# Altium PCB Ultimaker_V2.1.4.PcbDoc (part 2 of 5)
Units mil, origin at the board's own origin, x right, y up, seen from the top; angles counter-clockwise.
Board outline 6889.76 x 3110.24 mil, 4 copper layers (top, signal, Power, bot (thermal)), stack 67.717 mil thick; 574 components, 252 nets, 1322 pads, 511 vias.
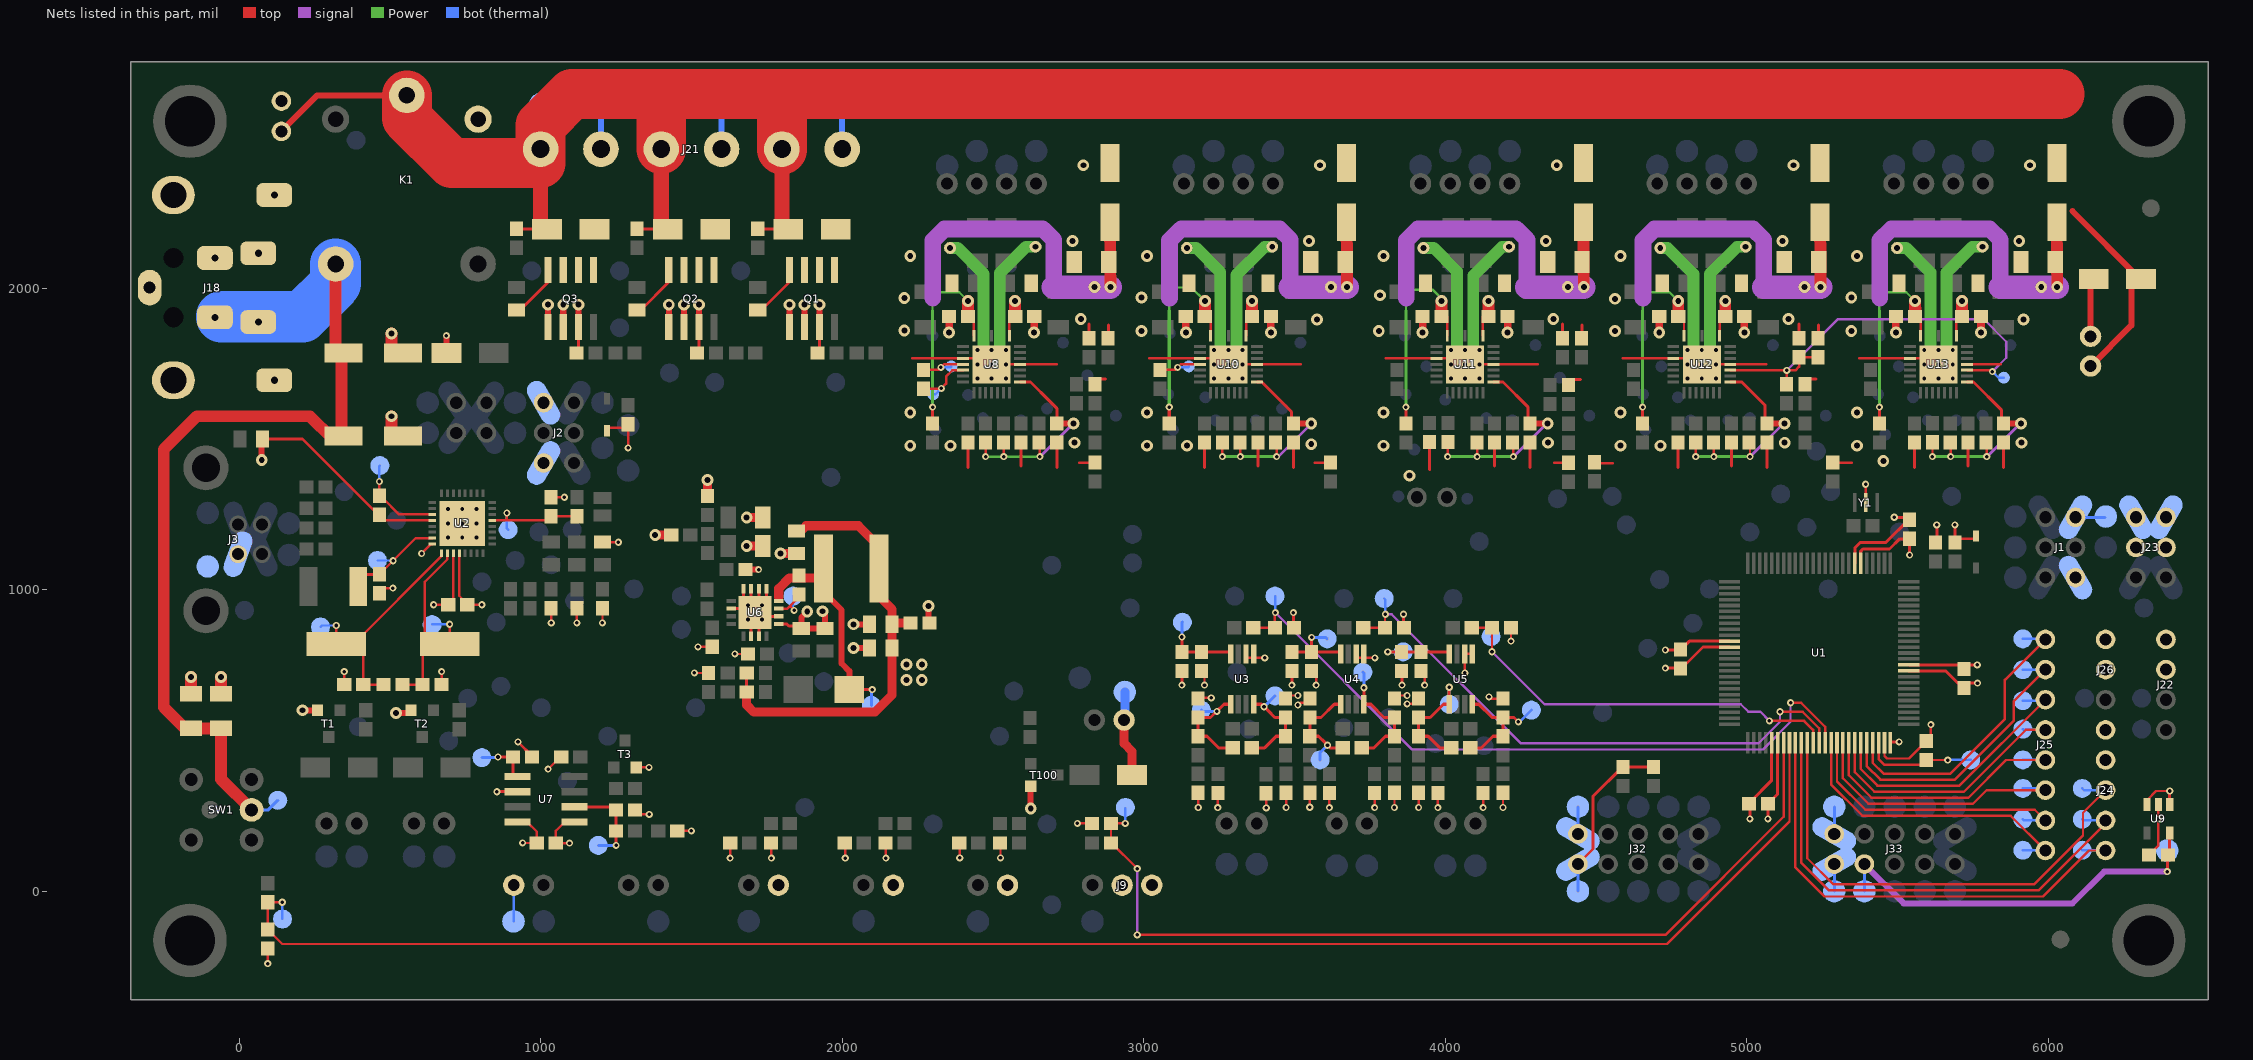
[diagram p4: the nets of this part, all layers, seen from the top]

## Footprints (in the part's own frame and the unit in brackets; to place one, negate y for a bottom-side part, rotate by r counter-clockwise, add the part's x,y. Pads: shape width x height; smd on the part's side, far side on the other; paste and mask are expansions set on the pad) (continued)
TSQFP50P1600X1600X120-100N [mm] "TSQFP, 100-Leads, Body 16.3x16.3mm (max), Pitch 0.50mm, IPC Medium Density"
  rect 1.8x0.3 smd: 1(-7.55,6) 2(-7.55,5.5) 3(-7.55,5) 4(-7.55,4.5) 5(-7.55,4) 6(-7.55,3.5) 7(-7.55,3) 8(-7.55,2.5) 9(-7.55,2) 10(-7.55,1.5) 11(-7.55,1) 12(-7.55,0.5) 13(-7.55,0) 14(-7.55,-0.5) 15(-7.55,-1) 16(-7.55,-1.5) 17(-7.55,-2) 18(-7.55,-2.5) 19(-7.55,-3) 20(-7.55,-3.5) 21(-7.55,-4) 22(-7.55,-4.5) 23(-7.55,-5) 24(-7.55,-5.5) 25(-7.55,-6) 51(7.55,-6) 52(7.55,-5.5) 53(7.55,-5) 54(7.55,-4.5) 55(7.55,-4) 56(7.55,-3.5) 57(7.55,-3) 58(7.55,-2.5) 59(7.55,-2) 60(7.55,-1.5) 61(7.55,-1) 62(7.55,-0.5) 63(7.55,0) 64(7.55,0.5) 65(7.55,1) 66(7.55,1.5) 67(7.55,2) 68(7.55,2.5) 69(7.55,3) 70(7.55,3.5) 71(7.55,4) 72(7.55,4.5) 73(7.55,5) 74(7.55,5.5) 75(7.55,6)
  rect 0.3x1.8 smd: 26(-6,-7.55) 27(-5.5,-7.55) 28(-5,-7.55) 29(-4.5,-7.55) 30(-4,-7.55) 31(-3.5,-7.55) 32(-3,-7.55) 33(-2.5,-7.55) 34(-2,-7.55) 35(-1.5,-7.55) 36(-1,-7.55) 37(-0.5,-7.55) 38(0,-7.55) 39(0.5,-7.55) 40(1,-7.55) 41(1.5,-7.55) 42(2,-7.55) 43(2.5,-7.55) 44(3,-7.55) 45(3.5,-7.55) 46(4,-7.55) 47(4.5,-7.55) 48(5,-7.55) 49(5.5,-7.55) 50(6,-7.55) 76(6,7.55) 77(5.5,7.55) 78(5,7.55) 79(4.5,7.55) 80(4,7.55) 81(3.5,7.55) 82(3,7.55) 83(2.5,7.55) 84(2,7.55) 85(1.5,7.55) 86(1,7.55) 87(0.5,7.55) 88(0,7.55) 89(-0.5,7.55) 90(-1,7.55) 91(-1.5,7.55) 92(-2,7.55) 93(-2.5,7.55) 94(-3,7.55) 95(-3.5,7.55) 96(-4,7.55) 97(-4.5,7.55) 98(-5,7.55) 99(-5.5,7.55) 100(-6,7.55)
  silkscreen extent -7.68,-6.25 6.25,6.82, body extent -8.01,-8.01 8.01,8.01, height 1.1
XT49M-2016M [mm]
  rect 5x2 smd: 1(-4.775,0) 2(4.775,0)
  silkscreen extent -6.35,-2.35 6.35,2.35, body extent -6.35,-2.35 6.35,2.35, height 4.2

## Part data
C1 C7 C9: library part Library_CAP-0008, "RO C0G 22pF 2% 50V  0603"
C2 C3 C4 C5 C8 C10 C11 C12 C13 C14 C17 C18 C19 C20 C22 C24 C25 C26 C29 C31 C32 C40 C41 C42 C43 C44 C45 C57 C58 C59 C61 C62 C63 C65 C66 C67 C68 C69 C70 C71 C79 C80 C81 C83 C84 C85 C91 C92 C100 C101 C102 C103 C104 C105 C110 C113 C116: library part Library_CAP-0002, "RO X7R 100nF 10% 50V 0603"
C6 C15 C21 C27 C35 C46 C47 C50 C51 C72 C73: library part Library_CAP-0006, "RO X5R 1uF 10% 10V 0603"
C16 C23 C28 C33 C90 C117: library part Library_CAP-0007, "RO X7R 10nF 10% 50V 0603"
C30 C114: library part Library_CAP-0011, "RO X7R 22nF 10% 0603 50V CC0603KRX7R9BB223"
C36 C37 C53 C54 C55 C76 C77: library part Library_CAP-0004, "RO ELCO 100uF 20% 35V CASE-D EEEFP PAN"
C38 C39: library part Library_CAP-0005, "RO X5R 10UF 10% 35V 1206"
C48 C49 C52 C74 C75: library part Library_CAP-0001, "RO X7R 220nF 10% 25V  0603"
C56 C60 C64 C78 C82: library part Library_CAP-0003, "RO X7R 4,7uF 10% 50V 1206"
C86 C87 C115: library part Library_CAP-0012, "6R3R15X106KV4E - MLCC, 0805, X5R, 6.3V, 10UF"
C88: library part Library_CAP-0013, "RO C0G 1nF 5% 50V 0603"
C111 C112: "X7R 1uF 10% 50V 1206 GRM31"
D1 D2: library part Library_DIO-0002, "RO DIODE 1N4148WS-V-GS08 SOT-323  VISHAY"
D3 D4: library part Library_LED-0003, "RO LED GEEL HSMY-C170 0805  AVAGO"
D5 D6 D8 D9 D13 D14 D15 D100: library part Library_DIO-0001, "RO DIODE S1G DO-214AC"
D7: library part Library_LED-0002, "RO LED GROEN HSMG-C170 0805 AVAGO"
D10 D11 D12: library part Library_LED-0001, "RO LED ROOD HSMH-C170 0805 AVAGO"
D16: library part Library_DIO-0003, "RO DIODE SSB44-E3/52T SMB VISHAY"
F1: library part Library_FUSE-0001, "RO ZEK MULTI 500MA SMD 1812 MF-MSMF050-2 BOURNS"
Fid1 Fid2 Fid3: library part Library_MISC-0003
J1 J2 J23: library part Library_CON-0003, "RO CONN PR HDR 2X3P H4B-06DS-0000 INT"
J3: library part Library_CON-0001, "RO CONN PR USB-B HKS 61729-1011BLF FCI"
J4: library part Library_CON-0011, "HDR 2X2P"
J5 J6 J8 J16 J17 J20: library part Library_CON-0004, "RO CONN PR 2p HKS S2B-XH-A (LF)(SN) JST"
J7 J11 J13 J14 J15: library part Library_CON-0006, "RO CONN PR 2p HKS 22-05-7028 MOLEX"
J9: library part Library_CON-0020, "RO CONN PR 3p HKS S3B-XH-A (LF)(SN) JST"
J18: library part Library_CON-0009, "RO CONN PR KPJX-4S-S KYCON"
J19: library part Library_CON-0013, "HEADER-1x2P-ST-2.54"
J21: library part Library_CON-0008, "RO CONN PR 6p MC000038 MULTICOMP"
J22: library part Library_CON-0014, "HEADER-1x4P-ST-2.54"
J24: library part Library_CON-0015, "HEADER-1x5P-ST-2.54"
J25: library part Library_CON-0016, "HEADER-1x8P-ST-2.54"
J26: library part Library_CON-0017, "HEADER-1x3P-ST-2.54"
J27 J28 J29 J30 J31: library part Library_CON-0005, "RO CONN PR 4p HKS S4B-XH-A (LF)(SN) JST"
J32 J33: library part Library_CON-0019, "RO CONN PR HDR BOX 10p HKS 61201021721 WUERTH"
J34: "CONN PR 2p B2B-XH-A JST"
JP2: library part Library_CON-0010
JP3: library part Library_CON-0018, "HEADER-1x2P-ST-2.54"
K1: library part Library_REL-0001, "RO REL 5V HRS4-S DC5V MULTICOMP"
L1: library part Library_COIL-0001, "RO FERRIET BLM21PG221SN1D  0805"
L2: library part Library_COIL-0002, "RO SPOEL 6,3uH 20% NRS6045T 6R3MMGK TAIYO YUDEN"
L100: "FERRIET BLM18PG121SN1D 0603 MURATA"
L120 L121 L122 L123 L130 L131 L132 L133 L140 L141 L142 L143 L150 L151 L152 L153 L160 L161 L162 L163: "FERRIET 742792118 1206 Wurth Elektronik"
Q1 Q2 Q3: library part LIBRARY_FET-0002, "IRF8736PBF - MOSFET, N SO-8"
R1 R2 R3 R5 R20 R23 R31 R34 R38 R41 R46 R84 R85 R86 R102 R103: library part Library_RES-0001, "RO RES 10k0 1% 0,063W  0603"
R4 R10: library part Library_RES-0003, "RO RES 1M0 1% 0,1W 0603"
R6 R7: library part Library_RES-0007, "RO RES 22E0 1% 0,063W 0603"
R8 R9: library part Library_RES-0012, "RO VDR 0603 CG0603MLC-05E"
R11 R12 R13 R14 R15 R18 R26 R30 R43 R44 R45 R47 R48 R51 R52 R53 R69 R70 R71 R72 R93 R94 R109 R111 R120: library part Library_RES-0004, "RO RES 1k0 1% 0,1W  0603"
R16 R25 R28 R50 R61 R63 R65 R88 R90: library part Library_RES-0002, "RO RES 4k70 1% 0,063W  0603"
R17 R21 R27 R32 R36 R39 R54 R55 R56: library part Library_RES-0006, "RO RES 100E 1% 0,063W  0603"
R19 R24 R29 R35 R37 R42: library part Library_RES-0010, "RO RES 2k2 0,1% 0,063W 25ppm 0603"
R22 R33 R40: library part Library_RES-0011, "RO RES 5K49 0,1% 0,063W 25ppm 0603"
R49 R57 R58 R59 R60 R62 R64 R66 R67 R68 R87 R89 R91 R92 R104: library part Library_RES-0005, "RO RES 100k0 1% 0,063W  0603"
R73 R78 R95: library part Library_RES-0018, "RO RES 604E 1% 0,063W 0603"
R74 R75 R76 R77 R79 R80 R96 R97 R98 R99: library part Library_RES-0013, "RO RES 0E05 1% 0,125W 0805"
R81 R82 R83 R100 R101: library part Library_RES-0001
R105: library part Library_RES-0017, "RO RES 47E 1% 0,063W 0603"
R106 R107: library part Library_RES-0016, "RES 0E10 1% 0,125W 0805"
R108: library part Library_RES-0014, "RO RES 3k92 1% 0.063W 0603"
R110: library part Library_RES-0015, "RO RES 750E 1% 0,063W 0603"
SP1: "MOER-SMD SMTSO-M3-10ET  PEM"
SP2 SP3 SP4: "Spacer SMTSO-M3-10ET"
SW1: library part Library_SWI-0001, "Rocker switch,SPDT,on-none-on,RA,snap-in"
T1 T2 T100: library part Library_TRA-0001, "RO TRANS BC817-25  SOT-23"
T3: library part Library_TRA-0002, "RO TRANS BC807-40  SOT-23"
TP1 TP2 TP3 TP4 TP5 TP6 TP7 TP8 TP9 TP10 TP11 TP12 TP13 TP14 TP15 TP16 TP17 TP18 TP19 TP20 TP21 TP22 TP23 TP24 TP25 TP26 TP27 TP28 TP29 TP30 TP31 TP32 TP33 TP34 TP35 TP36 TP37 TP38 TP39 TP40 TP41 TP42 TP43 TP44 TP45 TP46 TP47 TP48 TP49 TP50 TP51 TP52 TP53 TP54 TP55 TP56 TP57 TP58 TP59 TP60 TP61 TP62 TP63 TP64 TP65 TP66 TP67 TP68 TP69 TP70 TP71 TP72 TP73 TP74 TP75 TP76 TP77 TP78 TP79 TP80 TP100 TP101: library part Library_MISC-0001
U1: library part Library_ICS-0001, "RO IC ATMEGA2560-16AU TQFP-100 ATMEL"
U2: library part Library_ICS-0004, "RO IC ATMEGA16U2-MU QFN-32 ATMEL"
U3 U4 U5: library part Library_ICS-0003, "RO IC INA826AIDGKR MSOP-8 TI"
U6: library part Library_ICS-0010, "RO IC A4403GEUTR-T QFN-16 ALLEGRO"
U7: library part Library_ICS-0009, "RO IC NE555D SO-08 TI"
U8 U10 U11 U12 U13: library part Library_ICS-0002, "RO IC A4988 QFN-28 ALLEGRO"
U9: library part Library_ICS-0008, "RO STABI LP2985A-33DBVTE4 SOT-23-5 TI"
Y1: library part LIBRARY_XTAL-0002, "RO KRIS 16MHz CSTCE16M0V53-R0 SMD MURATA"
Y2: library part LIBRARY_XTAL-0001, "RO KRISTAL 16.0MHz  HC49/4HSMX  SMD CMAC"

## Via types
v1: diameter 23.62, hole 11.81, top to bot (thermal), tented bottom, 172 vias
v2: diameter 23.62, hole 11.81, top to bot (thermal), tented both sides, 104 vias
v3: diameter 39.37, hole 19.68, top to bot (thermal), tented bottom, 88 vias
v4: diameter 25.98, hole 12.99, top to bot (thermal), tented bottom, 58 vias
v5: diameter 23.62, hole 11.81, top to bot (thermal), 46 vias
v6: diameter 39.37, hole 19.68, top to bot (thermal), tented both sides, 43 vias

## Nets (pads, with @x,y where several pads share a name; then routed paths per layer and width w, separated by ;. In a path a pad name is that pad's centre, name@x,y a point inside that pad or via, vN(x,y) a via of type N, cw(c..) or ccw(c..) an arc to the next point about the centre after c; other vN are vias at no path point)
+3V3: C35.2 J33.8 TP17.1 TP37.1 U9.5 | length 1377.9
  top w10: v1(6394.37,65.16) C35.2@6394.37,117.87 ; C35.2@6402.4,120 U9.5@6402.4,192.76
  signal w20: J33.8@5390,90 5520,-40 6080,-40 6185,65 v1@6394.37,65
  bot (thermal) w10: TP37.1@5390,0 J33.8@5390,90 ; v1@6394.37,60.16 6394.37,117.87 TP17.1@6396.5,120
+5V: C3.2 C4.2 C5.2 C10.2 C31.2 C59.2 C63.2 C67.2 C81.2 C85.2 C86.2 C87.2 C90.2 C91.2 C100.2 C102.2 C104.2 C115.2 C116.2 D1.2 D2.2 D100.2 J1.2@6090,1240 J2.2@1010,1420 J9.2 J16.1 J22.1 J23.3 J23.4@6390,1140 J24.2 J26.1 J32.10 J33.10 J34.1 L2.2 R1.1 R2.1 R3.2 R5.1 R11.2 R12.2 R16.2 R17.1 R19.1 R25.2 R27.1 R28.2 R29.1 R36.1 R37.1 R45.2 R46.2 R60.2 R61.2 R62.2 R63.2 R64.2 R65.2 R81.2 R82.2 R83.2 R87.2 R88.2 R89.2 R90.2 R100.2 R101.2 R108.2 T3.2 TP16.1 TP18.1 TP22.1 TP45.1 TP100.1 U1.10 U1.31 U1.61 U1.80 U1.100 U2.4 U2.32 U7.8 U8.15 U9.1 U9.3 U10.15 U11.15 U12.15 U13.15 | length 9022
  top w8: v1(605,1120) 636.1,1151.1 U2.32@640.59,1151.1 ; U2.4@730.16,1120.59 730.16,979.84 756.5,953.5 C10.2@756.5,950 v1(805,950) ; U7.8@923.74,230 955,230 987.01,197.99 C31.2@987.01,160 v1(940,160) ; v1(1025,405) 1065,445 R46.2@1068.5,445 ; v1(1035,890) R11.2@1035,938.5 ; v1(1120,890) R12.2@1120,938.5 ; v1(1205,890) R45.2@1205,938.5 ; D2.2@1216.06,1536.69 1278.19,1536.69 R5.1@1290,1548.5 v1(1290,1470) ; T3.2@1317.4,410.71 v1(1359.29,410.71) ; v1(1628.5,110) R16.2@1628.5,160 ; v1(2010,110) R25.2@2010,155 ; R28.2@2388.5,160 2390,158.5 v1(2390,110.56) ; v1(2475.64,1441.39) R61.2@2475.64,1488.39 ; v1@2535.64,1437.39 R81.2@2535.64,1488.39 ; v1@2655.64,1437.39 R60.2@2655.64,1488.39 ; v1(3260.64,1441.39) R63.2@3260.64,1488.39 ; v1(3320.64,1441.39) R82.2@3320.64,1488.39 ; v2(3406.16,276.36) C100.2@3406.16,324.87 ; v1(3440.64,1441.39) R62.2@3440.64,1488.39 ; v2(3472.02,277.63) R19.1@3472.02,326.13 ; v2(3765.64,277.39) C102.2@3765.64,325.9 ; v2(3831.5,277.63) R29.1@3831.5,326.13 ; v1(4007.64,1441.39) R65.2@4007.64,1488.39 ; v1(4105.64,1441.39) R83.2@4105.64,1488.39 ; v2(4125.64,277.39) C104.2@4125.64,325.9 ; v2(4191.5,277.63) R37.1@4191.5,326.13 ; v1(4225.64,1441.39) R64.2@4225.64,1488.39 ; v1(4830.64,1441.39) R88.2@4830.64,1488.39 ; v1@4890.64,1437.39 R100.2@4890.64,1488.39 ; v1@5010.64,1437.39 R87.2@5010.64,1488.39 ; v1(5615.64,1441.39) R90.2@5615.64,1488.39 ; v1@5675.64,1437.39 R101.2@5675.64,1488.39 ; R3.2@5701.81,1168.31 D1.2@5763.94,1168.31 ; v1@5795.64,1437.39 R89.2@5795.64,1488.39 ; U9.3@6327.6,287.24 6330,289.65 6330,305 6357.4,332.4 v1(6402.4,332.4)
  top w10: C90.2@1683.31,660.78 R108.2@1683.31,723.77 ; U8.15@2590.13,1688.34 2624.81,1688.34 2689.64,1623.51 2689.64,1623.39 2711.64,1601.39 C59.2@2711.64,1551.39 ; v1(3126.5,683.66) R17.1@3126.5,730.67 ; U10.15@3375.12,1688.34 3391.54,1688.34 3490,1589.88 3490,1554.88 C63.2@3485,1549.88 ; v2(3491.5,683.66) R27.1@3491.5,730.67 ; v2(3856.5,683.66) R36.1@3856.5,730.67 ; U11.15@4160.12,1688.34 4191.54,1688.34 4275,1604.88 C67.2@4275,1549.88 ; J32.10@4440,90 4490,140 4490,315 4586.5,411.5 R1.1@4690,411.5 ; v1@4730,805 4735,800 4780,800 4809.37,829.37 U1.61@4942.76,829.37 ; U12.15@4945.12,1688.34 4983.46,1688.34 5060,1611.8 C81.2@5060,1549.88 ; v1@5010.42,240 5010.42,295.42 5082.52,367.52 U1.80@5082.52,492.76 ; U1.31@5377.8,1087.24 5377.8,1127.8 5384.68,1134.68 5473.47,1134.68 5507.3,1168.5 C3.2@5540,1168.5 v2(5540,1115) ; U1.100@5478.98,495 v1(5505,495) ; U1.10@5535.94,730.94 U1.10@5537.24,730.94 5659.06,730.94 C5.2@5718.25,671.75 ; R3.2@5690,1156.5 v1(5690,1215) ; C5.2@5720,673.5 5736.5,690 v1(5765,690) ; U13.15@5730.12,1688.34 5751.54,1688.34 5845,1594.88 C85.2@5845,1549.88 ; U9.3@6325,289.84 U9.3@6327.6,287.24 ; U9.1@6402.4,287.24 v1(6402.4,332.4)
  top w20: C59.2@2711.64,1551.39 v3@2766.65,1551.39 ; C63.2@3496.64,1551.39 v3@3556.65,1551.39 ; C67.2@4281.64,1551.39 v3@4336.65,1551.39 ; C81.2@5066.64,1551.39 v3@5121.65,1551.39 ; C85.2@5851.64,1551.39 v3@5906.65,1551.39
  top w30: C90.2@1683.31,660.78 1683.31,617.47 1706.93,593.85 2108.51,593.85 2165.59,650.94 C86.2@2165.59,806.45 C87.2@2165.59,885.19 C87.2@2165.59,889.13 ; C115.2@1848.66,1194.24 1862.44,1194.24 1880.16,1211.96 2053.39,1211.96 L2.2@2122.29,1143.06 ; L2.2@2122.29,977.71 2165.59,934.4 C87.2@2165.59,889.13 ; C116.2@2214.81,889.13 C87.2@2165.59,889.13 ; J34.1@2934.85,567.51 2934.85,489.95 2960.87,463.93 D100.2@2960.87,385.19
  signal w10: v1@2656.65,1441.39 v3@2766.65,1551.39 ; v1@3446.65,1441.39 v3@3556.65,1551.39 ; v1@4226.65,1441.39 v3@4336.65,1551.39 ; v1@5011.65,1441.39 v3@5121.65,1551.39 ; v1@5796.65,1441.08 v3@5906.64,1551.07
  Power w8: v1(2475.64,1441.39) v1(2655.64,1441.39)
  Power w10: v1(3260.64,1441.39) v1@3446.65,1441.39 ; v1(4007.64,1441.39) v1@4226.65,1441.39 ; v1(4830.64,1441.39) v1@5011.65,1441.39 ; v1(5615.64,1441.39) v1@5796.65,1441.39
  bot (thermal) w8: TP18.1@910.79,-99.21 J16.1@910.79,20
  bot (thermal) w10: J32.10@4430,80 J32.10@4440,90 TP22.1@4440,0 ; TP45.1@5290,0 J33.10@5290,90 ; J1.2@6090,1240 TP16.1@6188.12,1240
  bot (thermal) w30: J34.1@2934.85,567.51 2937.25,569.91 TP100.1@2937.25,660.78
  other v1: 5010,240 4730,800 2535.64,1441.39 4890.64,1441.39 5010.64,1441.39 5675.64,1441.39 5795.64,1441.39
  other v3: 2212.84,700.15 2264.02,700.15 2212.84,751.33 2264.02,751.33 2767,1550.88 3555.64,1550.88 4339.64,1550.88 5124.64,1550.88 5909.64,1550.88
+24V: C43.2 C44.2 C45.2 C53.1 C54.1 C55.1 C56.2 C57.2 C58.2 C60.2 C61.2 C62.2 C64.2 C65.2 C66.2 C70.2 C71.2 C76.1 C77.1 C78.2 C79.2 C80.2 C82.2 C83.2 C84.2 D9.2 D13.2 D14.2 D15.2 J19.1 J20.1 J21.2 J21.4 J21.6 K1.3 R51.2 R52.2 R53.2 TP21.1 TP43.1 U8.22 U8.28 U10.22 U10.28 U11.22 U11.28 U12.22 U12.28 U13.22 U13.28 | length 18574.8
  top w8: U8.28@2436.58,1841.88 C58.2@2436.58,1904.94 ; U8.22@2554.69,1841.88 C57.2@2554.69,1904.94 ; U10.28@3221.58,1841.88 C62.2@3221.58,1904.94 ; U10.22@3339.69,1841.88 C61.2@3339.69,1904.94 ; U11.28@4006.58,1841.88 C66.2@4006.58,1904.94 ; U11.22@4124.69,1841.88 C65.2@4124.69,1904.94 ; U12.28@4791.58,1841.88 C80.2@4791.58,1904.94 ; U12.22@4909.69,1841.88 C79.2@4909.69,1904.94 ; U13.28@5576.58,1841.88 C83.2@5576.58,1904.94 ; U13.22@5694.69,1841.88 C84.2@5694.69,1904.94
  top w10: R53.2@920,2196.5 D15.2@1019.76,2196.5 ; R52.2@1320,2196.5 D14.2@1419.76,2196.5 ; R51.2@1720,2196.5 D13.2@1819.76,2196.5 ; C43.2@2299.64,1551.39 v1(2299.64,1605.39) ; C44.2@3084.64,1551.39 v1(3084.64,1605.39) ; C45.2@3869.64,1551.39 v1(3869.64,1605.39) ; C70.2@4654.64,1551.39 v1(4654.64,1605.39) ; C71.2@5439.64,1551.39 v1(5439.64,1605.39)
  top w20: J19.1@140,2520 259.06,2639.06 K1.3@556.22,2639.06 ; 6080,2255 6305,2030 6275,2030 6275,1876.57 J20.1@6140,1741.57
  top w39.37: C58.2@2417.64,1905.9 v6(2417.64,1957.39) ; C57.2@2573.64,1905.9 v6(2573.64,1957.39) ; C53.1@2888,2218.46 2888.82,2086.01 v3(2889.34,2003.3) ; C62.2@3202.64,1905.9 v6(3202.64,1957.39) ; C61.2@3358.64,1905.9 v6(3358.64,1957.39) ; C54.1@3673,2218.46 3673.82,2086.01 v3(3674.33,2003.3) ; C66.2@3987.64,1905.9 v6(3987.64,1957.39) ; C65.2@4143.64,1905.9 v6(4143.64,1957.39) ; C55.1@4458,2218.46 4458.82,2086.01 v3(4459.33,2003.3) ; C80.2@4772.64,1905.9 v6(4772.64,1957.39) ; C79.2@4928.64,1905.9 v6(4928.64,1957.39) ; C76.1@5243,2218.46 5243.82,2086.01 v3(5244.33,2003.3) ; C83.2@5557.64,1905.9 5557.64,1931.88 ; v6(5557.64,1957.39) 5557.64,1931.88 ; 5559.91,1931.88 5557.64,1931.88 ; C84.2@5713.64,1905.9 v6(5713.64,1957.39) ; C77.1@6028,2218.46 6028.82,2086.01 v3(6029.33,2003.3)
  top w50: D15.2@1000,2196.5 J21.6@1000,2461 ; D14.2@1400,2196.5 J21.4@1400,2461 ; D13.2@1800,2196.5 J21.2@1800,2460
  top w165.35: K1.3@556.22,2639.06 556.22,2563.78 705,2415 1000,2415 1000,2540 1103.94,2643.94 1400,2643.94 ; J21.4@1400,2461 1400,2643.94 ; J21.2@1800,2460 1800,2638.94 1805,2643.94 ; 6037,2643.94 1805,2643.94 ; 1400,2643.94 1805,2643.94
  signal w55.12: 2300.64,1967.39 2300.64,2158.03 2338.82,2196.21 2665.59,2196.21 2701.03,2160.78 2701.03,2003.3 ; 3085.64,1967.39 3085.64,2158.03 3123.82,2196.21 3450.59,2196.21 3486.03,2160.78 3486.03,2003.3 ; 3870.64,1967.39 3870.64,2158.03 3908.82,2196.21 4235.59,2196.21 4271.03,2160.78 4271.03,2003.3 ; 4655.64,1967.39 4655.64,2158.03 4693.82,2196.21 5020.59,2196.21 5056.03,2160.78 5056.03,2003.3 ; 5440.64,1967.39 5440.64,2158.03 5478.82,2196.21 5805.59,2196.21 5841.03,2160.78 5841.03,2003.3
  signal w78.74: 2701.03,2003.3 v3(2889.34,2003.3) ; 3486.03,2003.3 v3(3674.33,2003.3) ; 4271.03,2003.3 v3(4459.33,2003.3) ; 5056.03,2003.3 v3(5191.33,2003.3) v3(5244.33,2003.3) ; 5841.03,2003.3 v3(6029.33,2003.3)
  Power w8: 2299.64,1925.39 2299.64,1968.93 2317.17,1986.46 2388.03,1986.46 2417.09,1957.39 v6(2417.64,1957.39) ; 3084.64,1925.39 3084.64,1982.28 3104.57,2002.2 3157.83,2002.2 v6(3202.64,1957.39) ; 3869.64,1925.39 3869.64,1979.87 3884.09,1994.33 3958.9,1994.33 3987.64,1965.59 v6(3987.64,1957.39) ; 4654.64,1925.39 4654.64,1969.6 4671.5,1986.46 4743.57,1986.46 v6(4772.64,1957.39) ; 5439.64,1925.39 5439.64,1967.2 5458.9,1986.46 5528.57,1986.46 v6(5557.64,1957.39)
  Power w10: v1(2299.64,1605.39) 2299.64,1925.39 ; v1(3084.64,1605.39) 3084.64,1925.39 ; v1(3869.64,1605.39) 3869.64,1925.39 ; v1(4654.64,1605.39) 4654.64,1925.39 ; v1(5439.64,1605.39) 5439.64,1925.39
  bot (thermal) w20: J21.6@1000,2461 TP43.1@1000,2610 ; J21.4@1400,2461 TP21.1@1400,2610
  other v3: 2836.34,2003.3 3621.33,2003.3 4406.33,2003.3 5976.33,2003.3
ADC0: J25.1 TP132.1 U1.97 | length 990.2
  top w8: U1.97@5417.17,492.76 5417.17,425.98 5453.15,390 5675,390 5855.64,570.64 5855.64,700.64 J25.1@5990,835
  bot (thermal) w8: TP132.1@5915.59,836.85 5988.15,836.85 J25.1@5990,835
ADC1: J25.2 TP133.1 U1.96 | length 952.4
  top w8: U1.96@5397.48,492.76 5397.48,415.67 5443.15,370 5690,370 5885.64,565.64 5885.64,630.64 J25.2@5990,735
  bot (thermal) w8: TP133.1@5915.59,734.49 5989.49,734.49 J25.2@5990,735
ADC2: J25.3 TP134.1 U1.95 | length 916.2
  top w8: U1.95@5377.8,492.76 5377.8,405.35 5433.15,350 5705,350 J25.3@5990,635
  bot (thermal) w8: TP134.1@5915.59,632.13 5987.13,632.13 J25.3@5990,635
ADC3: J25.4 TP135.1 U1.94 | length 917
  top w8: U1.94@5358.11,492.76 5358.11,395.04 5423.15,330 5720,330 5925,535 J25.4@5990,535
  bot (thermal) w8: TP135.1@5915.59,537.64 5918.23,535 J25.4@5990,535
ADC4: J25.5 TP136.1 U1.93 | length 916.9
  top w8: U1.93@5338.43,492.76 5338.43,384.72 5413.15,310 5735,310 5860,435 J25.5@5990,435
  bot (thermal) w8: TP136.1@5915.59,435.28 5989.72,435.28 J25.5@5990,435
ADC5: J25.6 TP137.1 U1.92 | length 920
  top w8: U1.92@5318.74,492.76 5318.74,374.41 5403.15,290 5750,290 5795,335 J25.6@5990,335
  bot (thermal) w8: TP137.1@5915.59,340.79 5984.21,340.79 J25.6@5990,335
ADC6: J25.7 TP138.1 U1.91 | length 948.9
  top w8: U1.91@5299.06,492.76 5299.06,364.09 5393.15,270 5955,270 J25.7@5990,235
  bot (thermal) w8: TP138.1@5915.59,238.43 5919.02,235 J25.7@5990,235
ADC7: J25.8 TP139.1 U1.90 | length 1015.1
  top w8: U1.90@5279.37,492.76 5279.37,353.78 5383.15,250 5875,250 J25.8@5990,135
  bot (thermal) w8: TP139.1@5915.59,136.06 5988.94,136.06 J25.8@5990,135
ADC8: C16.2 R21.2 TP140.1 U1.89 | length 2375.9
  top w8: R21.2@3362.99,873.66 C16.2@3435,873.66 3435,922.17 v1(3436.5,923.66) ; v1(5145,625) 5180,625 5259.68,545.31 U1.89@5259.68,492.76
  signal w8: v1(3436.5,923.66) 3890.16,470 5053.13,470 5145,561.87 v1(5145,625)
  bot (thermal) w8: TP140.1@3435.28,978.58 3436.5,977.36 v1(3436.5,923.66)
ADC9: C23.2 R32.2 TP141.1 U1.88 | length 1917.4
  top w8: R32.2@3727.99,873.66 C23.2@3800,873.66 3800,917.17 v1(3801.5,918.66) ; v1(5110,595) 5185,595 5240,540 U1.88@5240,492.76
  signal w8: v1(3801.5,918.66) 3821.97,918.66 4250.63,490 5038.13,490 5110,561.87 5110,585 v1@5105,590
  bot (thermal) w8: TP141.1@3797.48,970.71 3801.5,966.69 v1(3801.5,918.66)
ADC10: C28.2 R39.2 TP142.1 U1.87 | length 1423.8
  top w8: R39.2@4082.99,873.66 C28.2@4155,873.66 ; v1(4155,794.17) C28.2@4155,873.66 ; C28.2@4155,877.68 C28.2@4155,873.66 ; C28.2@4156.5,872.17 C28.2@4155,873.66 ; v1(5075,565) 5190,565 5220,535 ; U1.87@5220.32,492.76 5220.32,534.69
  signal w8: v1(4155,794.17) 4329.17,620 4980,620 5005,595 5045,595 v1(5075,565)
  bot (thermal) w8: TP142.1@4151.81,844.72 4155,841.54 v1(4155,794.17)
ADC11: J24.3 TP143.1 U1.86 | length 1662.1
  top w8: U1.86@5200.63,492.76 5200.63,109.37 5287.49,22.51 5952.51,22.51 6115,185 6115,260 J24.3@6190,335
  bot (thermal) w8: TP143.1@6112.44,340.79 6118.23,335 J24.3@6190,335
ADC12: J24.4 TP144.1 U1.85 | length 1626.8
  top w8: U1.85@5180.94,492.76 5180.94,94.06 5272.49,2.51 5967.51,2.51 6190,225 J24.4@6190,235
  bot (thermal) w8: TP144.1@6112.44,238.43 6115.87,235 J24.4@6190,235
ADC13: J24.5 TP145.1 U1.84 | length 1623.8
  top w8: U1.84@5161.26,492.76 5161.26,78.74 5257.49,-17.49 5982.51,-17.49 6135,135 J24.5@6190,135
  bot (thermal) w8: TP145.1@6112.44,136.06 6188.94,136.06 J24.5@6190,135
ADC14: R49.1 R50.2 TP146.1 U1.83 | length 5689.9
  top w8: v2(143.27,-36.5) R49.1@95,-36.5 R50.2@95,-127.01 142.99,-175 4735,-175 5141.57,231.57 U1.83@5141.57,492.76
  bot (thermal) w8: TP146.1@143.27,-91.61 v2(143.27,-36.5)
ADC15: C22.2 R30.2 TP147.1 U1.82 | length 3059.4
  top w8: v2(2938.9,225) C22.2@2891.5,225 R30.2@2891.5,160 2891.5,161.93 v1(2978.43,75) ; v1(2978.43,-145) 4730,-145 5121.89,246.89 U1.82@5121.89,492.76
  signal w8: v1(2978.43,-145) v1(2978.43,75)
  bot (thermal) w8: v2(2938.9,225) TP147.1@2938.9,275.47
AREF: C2.2 TP191.1 U1.98 | length 367.8
  top w8: U1.98@5436.85,492.76 5436.85,438.15 5455,420 C2.2@5595,420 ; C2.2@5595,435 v5(5666.19,435)
  bot (thermal) w8: v5(5666.19,435) 5666.46,435.28 TP191.1@5742.36,435.28
EXTRAREF: C73.2 R94.2 R95.2 TP503.1 U12.17 U13.17 | length 1448.4
  top w8: U12.17@4945.12,1727.71 v1@5132.63,1727.71 ; R94.2@5132.63,1685.89 v1(5132.63,1727.39) 5161.34,1727.39 5173.47,1739.52 R95.2@5173.47,1771.02 ; R95.2@5173.47,1771.39 C73.2@5236.46,1771.39 ; U13.17@5730.12,1727.71 5809.68,1727.71 v1@5814,1723.39
  signal w8: v1(5132.63,1727.39) 5302.32,1897.08 5785.63,1897.08 5860.47,1822.23 5860.47,1769.23 v1(5814.64,1723.39)
  bot (thermal) w8: v1(5814.64,1723.39) 5835.04,1702.99 TP503.1@5852.6,1702.99
GND: C1.1 C2.1 C3.1 C4.1 C5.1 C6.1 C7.1 C8.1 C9.1 C10.1 C12.1 C13.1 C14.2 C16.1 C17.1 C18.1 C19.1 C20.2 C22.1 C23.1 C24.1 C25.1 C26.2 C28.1 C29.1 C31.1 C32.1 C33.1 C35.1 C36.2 C37.2 C38.1 C39.1 C46.1 C47.1 C48.1 C49.1 C50.1 C51.1 C52.1 C53.2 C54.2 C55.2 C56.1 C57.1 C58.1 C59.1 C60.1 C61.1 C62.1 C63.1 C64.1 C65.1 C66.1 C67.1 C72.1 C73.1 C74.1 C75.1 C76.2 C77.2 C78.1 C79.1 C80.1 C81.1 C82.1 C83.1 C84.1 C85.1 C86.1 C87.1 C88.1 C91.1 C92.1 C101.1 C103.1 C105.1 C110.1 C111.1 C112.1 C113.1 C114.1 C115.1 C116.1 C117.1 D7.2 D8.1 D9.1 J1.4@6090,1040 J1.6 J2.4@1010,1620 J2.6 J3.4 J5.2 J6.2 J8.2 J9.3 J18.1 J18.3 J18.5 J19.2 J20.2 J22.2 J23.1 J23.2@6390,1240 J23.4@6290,1240 J24.1 J26.2 J32.9 J33.9 K1.2 L1.1 Q1.1 Q1.2 Q1.3 Q2.1 Q2.2 Q2.3 Q3.1 Q3.2 Q3.3 R15.2 R24.1 R35.1 R42.1 R48.1 R50.1 R57.2 R58.2 R59.2 R66.2 R67.2 R68.2 R73.1 R74.1 R75.1 R76.1 R77.1 R78.1 R79.1 R80.1 R84.1 R85.1 R86.1 R91.2 R92.2 R95.1 R96.1 R97.1 R98.1 R99.1 R102.1 R103.1 R106.1 R107.1 R110.1 T1.2 T2.2 T100.2 TP12.1 TP24.1 TP39.1 U1.11 U1.32 U1.62 U1.81 U1.99 U2.3 U2.28 U2.EXPAD U3.5 U3.6 U4.5 U4.6 U5.5 U5.6 U6.2 U6.6 U6.7 U6.9 U6.10 U6.13 U6.14 U6.15 U6.16 U6.EXPAD U7.1 U7.6 U8.3 U8.18 U8.EXPAD U9.2 U10.3 U10.18 U10.EXPAD U11.3 U11.18 U11.EXPAD U12.3 U12.18 U12.EXPAD U13.3 U13.18 U13.EXPAD Y1.2 | length 15902.8
  top w8: v1(95,-240) R50.1@95,-190 ; C7.1@348.5,685 v1(348.5,728.5) ; C8.1@465,988.5 481.5,1005 v1(510,1005) ; C6.1@468.25,1241.75 468.25,1236.75 475,1230 U2.28@640.59,1230 ; v1(645,950) C10.1@693.5,950 ; C9.1@671.5,685 v1(671.5,728.5) ; C10.1@710.47,950 U2.3@710.47,1120.59 ; R15.2@1035,1306.5 v2(1078.5,1306.5) ; v1(1095.64,159.51) 1050,159.51 C31.1@1050,160 1050,200 1080,230 U7.1@1112.72,230 ; D7.2@1205,1157.4 v1(1257.6,1157.4) ; C32.1@1312.99,270 1327.99,255 v1(1360,255) ; R48.1@1452.99,200 v1(1500,200) ; v2(1510.08,723.77) R110.1@1557.33,723.77 ; v2(1521.89,810.39) C114.1@1569.14,810.39 ; v2(1643.94,786.76) C88.1@1687.25,786.76 ; v1(1765,110) C13.1@1765,160 ; v1(2145,110) C18.1@2145,160 ; 2232.64,1767.08 U8.3@2401.15,1767.08 ; U8.3@2401.15,1766.4 U8.3@2401.15,1767.08 ; U8.EXPAD@2456.64,1767.08 U8.3@2401.15,1767.08 ; C92.1@2523.5,160 2525,158.5 v1(2525,110.56) ; v4(2542.88,1747.39) U8.18@2590.13,1747.39 2711.64,1747.39 ; v1(2780,225) C22.1@2828.5,225 ; 2786.5,1421.38 R66.2@2838,1421.38 ; 3017.64,1767.08 U10.3@3186.14,1767.08 ; v2(3180.68,277.63) R24.1@3180.68,326.13 ; C17.1@3182.84,641.09 v2(3223.98,641.09) ; U10.3@3186.15,1766.4 U10.3@3186.14,1767.08 ; v2(3201.5,683.66) C12.1@3201.5,730.67 ; U10.EXPAD@3241.64,1767.08 U10.3@3186.14,1767.08 ; v2(3245.64,277.39) C101.1@3245.64,325.9 ; v4(3327.88,1747.39) U10.18@3375.12,1747.39 3521.64,1747.39 ; U3.6@3340.63,773.66 v1(3401.5,773.66) ; C14.2@3470.64,638.89 3473.75,638.89 3483.83,648.97 v2(3511.39,648.97) ; v2(3511.39,617.47) 3519.26,625.35 3537.95,625.35 C24.1@3551.5,638.89 ; v2(3550.76,278.61) R35.1@3550.76,332.11 ; 3566.5,1421.38 R67.2@3620,1421.38 ; v2(3571.5,683.66) C19.1@3571.5,730.67 ; v2(3615.64,277.39) C103.1@3615.64,325.9 ; U4.6@3705.63,773.66 v1(3766.5,773.66) ; 3802.64,1767.08 U11.3@3971.14,1767.08 ; C20.2@3831.5,638.89 3841.57,648.97 v2(3873.59,648.97) ; v2(3873.59,621.41) 3894.02,621.41 C29.1@3911.5,638.89 ; v2(3911.5,277.63) R42.1@3911.5,326.13 ; v2(3931.5,683.66) C25.1@3931.5,730.67 ; 3947.64,1398.82 3948.82,1397.64 ; U11.3@3971.15,1766.4 U11.3@3971.14,1767.08 ; v2(3975.64,277.39) C105.1@3975.64,325.9 ; U11.EXPAD@4026.64,1767.08 U11.3@3971.14,1767.08 ; U5.6@4064.29,787.32 U5.5@4088.15,787.32 ; v1(4065,724.17) 4065,773.66 U5.6@4065.63,773.66 ; v4(4112.88,1747.39) U11.18@4160.12,1747.39 4306.64,1747.39 ; v1(4145,644.17) 4150.28,638.89 C26.2@4191.5,638.89 ; v1(4217.99,829.17) C28.1@4217.99,873.66 ; 4361.5,1421.38 R68.2@4405,1421.38 ; R91.2@4495,1419.88 4555,1419.88 ; 4587.64,1767.08 U12.3@4756.14,1767.08 ; U12.3@4756.15,1766.4 U12.3@4756.14,1767.08 ; U12.EXPAD@4811.64,1767.08 U12.3@4756.14,1767.08 ; v4(4897.88,1747.39) U12.18@4945.12,1747.39 5064.64,1747.39 ; R92.2@5285,1421.38 5348.5,1421.38 ; 5372.64,1767.08 U13.3@5541.14,1767.08 ; v5@5393.94,1341.88 v5(5393.94,1349.76) 5395,1348.7 Y1.2@5395,1288.5 ; U1.99@5456.54,492.76 5456.54,448.46 5465,440 5537.75,440 5582.75,485 C2.1@5595,485 ; U13.3@5541.15,1766.4 U13.3@5541.14,1767.08 ; C2.1@5595,497.99 5610.63,513.62 v1(5610.63,552.51) ; U13.EXPAD@5596.64,1767.08 U13.3@5541.14,1767.08 ; U13.18@5730.12,1747.39 5842.76,1747.39 ; C35.1@6333.5,120 6365,151.5 v1(6365,240) U9.2@6365,287.24
  top w10: L1.1@77.4,1500 210,1500 452.5,1257.5 C6.1@452.5,1247.5 ; v1(855,330) U7.6@923.74,330 ; v1(925,495) C33.1@972.5,447.5 ; R59.2@1125,1791.5 Q3.3@1125,1870.51 ; R58.2@1525,1791.5 Q2.3@1525,1870.51 ; U6.2@1632.13,937.35 U6.EXPAD@1687.25,937.35 ; U6.EXPAD@1672.48,962.94 U6.16@1672.48,1003.3 ; U6.6@1698.07,845.82 U6.EXPAD@1698.07,911.76 ; U6.EXPAD@1698.07,937.35 U6.15@1698.07,1003.3 ; U6.7@1723.66,845.82 U6.EXPAD@1723.66,900.94 ; U6.EXPAD@1723.66,911.76 U6.10@1789.61,911.76 ; U6.EXPAD@1723.66,937.35 U6.14@1723.66,1003.3 ; U6.EXPAD@1749.25,962.94 U6.13@1749.25,1003.3 ; U6.9@1789.61,886.17 1816.18,886.17 1823.07,879.28 R107.1@1864.41,879.28 ; R57.2@1925,1791.5 Q1.3@1925,1870.51 ; 2416.64,1404.39 C48.1@2416.64,1488.4 ; 2593.64,1409.39 R84.1@2593.64,1488.39 ; 2711.64,1404.39 C59.1@2711.64,1488.39 ; R73.1@2818.47,1834.01 2818.47,1881.02 ; C46.1@2832.64,1698.39 2872.64,1698.39 ; C47.1@2882.88,1826.51 2882.88,1877.31 ; 3201.64,1404.39 C49.1@3201.64,1488.4 ; 3378.64,1409.39 R85.1@3378.64,1488.39 ; C16.1@3496.5,875.16 v1(3496.5,923.66) ; 3496.64,1404.39 C63.1@3496.64,1488.39 ; C23.1@3861.5,870.16 v1(3861.5,918.66) ; 3947.64,1398.82 C52.1@3947.64,1489.39 ; 4163.64,1409.39 R86.1@4163.64,1488.39 ; 4281.64,1404.39 C67.1@4281.64,1488.39 ; R78.1@4388.47,1834.01 4388.47,1881.02 ; C50.1@4406.64,1696.39 4448.63,1696.39 ; C51.1@4452.88,1826.51 4452.88,1877.31 ; v1(4730,740) 4785,740 4854.68,809.69 U1.62@4942.76,809.69 ; 4771.64,1404.39 C74.1@4771.64,1488.4 ; 4948.64,1409.39 R102.1@4948.64,1488.39 ; 5066.64,1404.39 C81.1@5066.64,1488.39 ; v1(5070,240) C91.1@5070,290 5102.2,322.2 U1.81@5102.2,492.76 ; R95.1@5173.47,1834.01 5173.47,1881.02 ; C72.1@5190.65,1698.39 5228.64,1698.39 ; C73.1@5237.88,1826.51 5237.88,1877.31 ; U1.32@5358.11,1087.24 5358.11,1138.11 5376.84,1156.84 5461.84,1156.84 C3.1@5540,1235 ; v2(5489,1240) C3.1@5539,1240 ; U1.11@5537.24,750.63 v1(5764.37,750.63) ; C3.1@5540,1231.5 C3.1@5540,1235 ; C3.1@5540,1240 C3.1@5540,1235 ; 5556.64,1404.39 C75.1@5556.64,1488.4 ; C1.1@5630,1156.5 v1(5630,1215) ; 5733.64,1409.39 R103.1@5733.64,1488.39 ; 5851.64,1404.39 C85.1@5851.64,1488.39
  top w20: v3(75,1430) L1.1@75,1510 ; v3(210,600) T1.2@260,600 ; v3(520,591) T2.2@571,591 ; D8.1@687.52,1785 v1(687.52,1842.48) ; Q3.1@1025,1870.51 v3(1025,1945) ; Q3.2@1075,1870.51 v3(1075,1945) ; Q3.3@1125,1870.51 v3(1125,1945) ; Q2.1@1425,1870.51 v3(1425,1945) ; Q2.2@1475,1870.51 v3(1475,1945) ; Q2.3@1525,1870.51 v3(1525,1945) ; C113.1@1679.37,1066.29 v2(1722.68,1066.29) ; Q1.1@1825,1870.51 v3(1825,1945) ; Q1.2@1875,1870.51 v3(1875,1945) ; v6(1884.09,927.4) 1864.41,907.72 1864.41,879.28 R107.1@1864.41,871.41 R106.1@1943.15,871.41 1943.15,920.62 v6(1935.28,928.5) ; Q1.3@1925,1870.51 v3(1925,1945) ; v6(2037.64,806.45) C86.1@2082.92,806.45 ; v6(2037.64,885.19) C87.1@2082.92,885.19 ; C116.1@2285.67,900.94 v6(2285.67,946.21) ; v6(2625.24,273.97) T100.2@2625.24,347.79 ; J20.2@6140,1840 6140,2020 D9.1@6150,2030
  top w25: v3(2354.64,1853.39) C58.1@2354.64,1905.39 ; v3(2636.64,1853.39) C57.1@2636.64,1905.39 ; v3(3139.64,1853.39) C62.1@3139.64,1905.39 ; v3(3421.64,1853.39) C61.1@3421.64,1905.39 ; v3(3924.64,1853.39) C66.1@3924.64,1905.39 ; v3(4206.64,1853.39) C65.1@4206.64,1905.39 ; v3(4709.64,1853.39) C80.1@4709.64,1905.39 ; v3(4991.64,1853.39) C79.1@4991.64,1905.39 ; v3(5494.64,1853.39) C83.1@5494.64,1905.39 ; v3(5776.64,1853.39) C84.1@5776.64,1905.39
  top w30: v6(1379.92,1181.1) C117.1@1433.07,1181.1 ; C110.1@1553.39,1310.39 v6(1553.39,1363.54) ; v6(1683.31,1145.03) C111.1@1736.46,1145.03 ; v6(1683.31,1239.52) C112.1@1736.46,1239.52 ; v6(1795.51,1119.44) C115.1@1848.66,1119.44
  top w39.37: C38.1@-160,654.17 v3(-160,710) ; C39.1@-60,654.17 v3(-60,710) ; C36.2@505,1508.43 v3(505,1575) ; C37.2@505,1786.57 v3(505,1850)
  Power w8: J32.9@4440,190 J32.9@4440,215
  Power w39.37: v6(2357.84,2133.22) 2382.53,2133.22 2468.64,2047.11 2468.64,1992.39 2468.64,1813.39 ; 2522.64,1813.39 2522.64,2050.2 2609.6,2137.16 v6(2641.31,2137.16) ; v6(3142.84,2133.22) 3173.87,2133.22 3253.64,2053.45 3253.64,1813.39 ; 3307.64,1813.39 3307.64,2043.86 3400.94,2137.16 v6(3426.3,2137.16) ; v6(3927.84,2133.22) 3961.27,2133.22 4038.64,2055.85 4038.64,1813.39 ; 4092.64,1813.39 4092.64,2041.46 4188.34,2137.16 v6(4211.3,2137.16) ; v6(4712.84,2133.22) 4736.86,2133.22 4823.64,2046.44 4823.64,1813.39 ; 4877.64,1813.39 4877.64,2046.93 4967.87,2137.16 v6(4996.3,2137.16) ; v6(5497.84,2133.22) 5528.2,2133.22 5608.64,2052.78 5608.64,1813.39 ; 5662.64,1813.39 5662.64,2052.4 5747.39,2137.16 v6(5781.3,2137.16)
  bot (thermal) w10: J32.9@4440,190 TP24.1@4440,280 ; J33.9@5290,190 TP39.1@5290,280
  other v3: 3881.89,1377.95 5452.64,1426.39 2225.64,1477.39 2358.64,1477.39 3010.64,1477.39 3143.64,1477.39 3795.64,1477.39 4580.64,1477.39 4713.64,1477.39 5365.64,1477.39 3555.64,1482.39 2770.64,1487.39 4340.64,1487.39 5125.64,1487.39 5910.64,1487.39 2225.64,1587.39 3010.64,1587.39 3795.64,1587.39 4580.64,1587.39 5365.64,1587.39 3574.44,1896.39 5917.63,1896.39 2791.34,1897.64 4358.27,1897.64 5137.8,1897.64 2225.64,2106.39 3010.64,2106.39 3795.64,2106.39 4580.64,2106.39 5365.64,2106.39 2763.35,2156.84 3548.35,2156.84 4333.35,2156.84 5118.35,2156.84 5903.35,2156.84 2799.64,2407.39 3584.64,2407.39 4369.64,2407.39 5154.64,2407.39 5939.64,2407.39
  other v4: 1687.25,900.94 1734.49,900.94 1687.25,948.18 1734.49,948.18 692.76,1172.76 740,1172.76 787.24,1172.76 692.76,1220 740,1220 787.24,1220 692.76,1267.24 740,1267.24 787.24,1267.24 2448.39,1700.15 2495.64,1700.15 2542.88,1700.15 3233.39,1700.15 3280.63,1700.15 3327.88,1700.15 4018.39,1700.15 4065.63,1700.15 4112.88,1700.15 4803.39,1700.15 4850.63,1700.15 4897.88,1700.15 5588.39,1700.15 5635.63,1700.15 5682.88,1700.15 2448.39,1747.39 2495.64,1747.39 3233.39,1747.39 3280.63,1747.39 4018.39,1747.39 4065.63,1747.39 4803.39,1747.39 4850.63,1747.39 5588.39,1747.39 5635.63,1747.39 5682.88,1747.39 2448.39,1794.64 2495.64,1794.64 2542.88,1794.64 3233.39,1794.64 3280.63,1794.64 3327.88,1794.64 4018.39,1794.64 4065.63,1794.64 4112.88,1794.64 4803.39,1794.64 4850.63,1794.64 4897.88,1794.64 5588.39,1794.64 5635.63,1794.64 5682.88,1794.64
  other v6: 2992.13,1858.27 3779.53,1858.27 4562.99,1858.27 5346.46,1858.27 2205.95,1859.39 4562.99,1964.57 2205.95,1967.15 2992.13,1968.5 5346.46,1968.5 3783.46,1976.38
HEATED-BED: D10.2 D13.1 J21.1 Q1.5 Q1.6 Q1.7 Q1.8 TP40.1 | length 282.8
  top w10: D10.2@1720,1927.6 1732.6,1927.6 1825,2020 Q1.8@1825,2059.49
  bot (thermal) w20: J21.1@2000,2510 TP40.1@2000,2610
HEATER1: D12.2 D15.1 J21.5 Q3.5 Q3.6 Q3.7 Q3.8 TP42.1 | length 321.8
  top w10: D12.2@930,1927.6 932.6,1927.6 1025,2020 Q3.8@1025,2059.49
  bot (thermal) w20: J21.5@1200,2461 TP42.1@1200,2610
HEATER2: D11.2 D14.1 J21.3 Q2.5 Q2.6 Q2.7 Q2.8 TP41.1 | length 331.8
  top w10: D11.2@1320,1927.6 1332.6,1927.6 1425,2020 Q2.8@1425,2059.49
  bot (thermal) w20: J21.3@1600,2461 TP41.1@1600,2610
NetC6_2: C6.2 TP171.1 U2.27 | length 297
  top w8: C6.2@465,1311.5 v5(465,1358.7) ; C6.2@466.75,1303.25 476.75,1303.25 530.47,1249.53 U2.27@640.59,1249.53
  bot (thermal) w8: v5(465,1358.7) 465,1409.88 TP171.1@466.77,1411.65
NetC7_2: C7.2 R10.2 TP172.1 U2.1 Y2.2 | length 884.9
  top w8: v2(322.01,881.06) Y2.2@322.01,820 ; R10.2@478.5,685 C7.2@411.5,685 411.5,818.5 410,820 Y2.2@322.01,820 ; U2.1@671.1,1120.59 671.1,1111.1 380,820 Y2.2@322.01,820
  bot (thermal) w8: TP172.1@269.92,876.22 274.76,881.06 v2(322.01,881.06)
NetC8_2: C8.2 F1.2 TP167.1 U2.31 | length 347.9
  top w8: C8.2@465,1050 v2(510.88,1095.88) 585.79,1170.79 U2.31@640.59,1170.79
  top w10: F1.2@395,1050 C8.2@465,1050
  bot (thermal) w8: TP167.1@458.9,1096.69 510.07,1096.69 v2(510.88,1095.88)
NetC9_2: C9.2 R10.1 TP173.1 U2.2 Y2.1 | length 738.6
  top w8: R10.1@541.5,685 C9.2@608.5,685 608.5,818.5 610,820 Y2.1@697.99,820 v2(697.99,885.16) ; Y2.1@615.79,825.79 615.79,1025.79 690.79,1100.79 U2.2@690.79,1120.59
  bot (thermal) w8: TP173.1@641.06,885.16 v2(697.99,885.16)
NetC11_2: C11.2 R15.1 TP178.1 U2.13 | length 348
  top w8: U2.13@839.41,1229.84 888.03,1229.84 ; v2(888.03,1254.17) 888.03,1229.84 ; R15.1@1021.34,1229.84 888.03,1229.84 ; R15.1@1035,1243.5 C11.2@1120,1243.5
  bot (thermal) w8: v2(888.03,1254.17) 888.03,1202.99 TP178.1@891.97,1199.06
NetC12_2: C12.2 R17.2 TP204.1 U3.8 | length 254.3
  top w10: v5(3126.5,843.03) R17.2@3126.5,793.66 U3.8@3281.77,793.66
  bot (thermal) w10: v5(3126.5,843.03) 3126.5,890.28 TP204.1@3128.19,891.97
NetC14_1: C14.1 C15.2 R20.2 TP200.1 U3.4 | length 365.8
  top w10: C15.2@3357.99,475.66 3401.07,475.66 3439.3,513.89 R20.2@3470.64,513.89 C14.1@3470.64,575.9 3434.85,575.9 3410.88,599.86 v5(3398.88,611.87) 3390.75,620 U3.4@3364.88,620
  bot (thermal) w10: v5(3398.88,611.87) 3399.27,611.87 TP200.1@3435.28,647.87
NetC15_1: C15.1 C17.2 R23.2 TP202.1 U3.1 | length 386.6
  top w10: U3.1@3288.11,604.28 U3.1@3288.11,620 3265.88,620 v5(3242.46,596.58) 3221.78,575.9 C17.2@3180.64,575.9 R23.2@3180.64,513.89 3209.46,513.89 3247.69,475.66 C15.1@3295,475.66
  bot (thermal) w10: TP202.1@3191.18,600.63 3195.23,596.58 v5(3242.46,596.58)
NetC19_2: C19.2 R27.2 TP210.1 U4.8 | length 257.2
  top w10: R27.2@3491.5,793.66 U4.8@3646.77,793.66 ; C19.2@3556.5,793.66 v5(3556.5,841.61)
  bot (thermal) w10: v5(3556.5,841.61) 3603.74,841.61 TP210.1@3608.5,836.85
NetC20_1: C20.1 C21.2 R31.2 TP206.1 U4.4 | length 414.2
  top w10: C21.2@3722.99,475.66 3763.28,475.66 3801.5,513.89 R31.2@3831.5,513.89 C20.1@3831.5,575.9 3797.06,575.9 3752.95,620 U4.4@3729.88,620 v5(3729.88,674.76)
  bot (thermal) w10: TP206.1@3726.61,726.61 3729.88,723.35 v5(3729.88,674.76)
NetC21_1: C21.1 C24.2 R34.2 TP208.1 U4.1 | length 366.4
  top w10: U4.1@3653.11,620 3632.02,620 3587.92,575.9 C24.2@3551.5,575.9 3551.5,514.75 R34.2@3550.64,513.89 3579.54,513.89 3599.86,493.57 v5(3609.36,484.06) 3617.76,475.66 C21.1@3660,475.66
  bot (thermal) w10: TP208.1@3584.88,435.28 3584.88,459.59 v5(3609.36,484.06)
NetC25_2: C25.2 R36.2 TP216.1 U5.8 | length 256.4
  top w10: v5(3809.4,793.65) R36.2@3854.5,793.65 ; R36.2@3846.5,793.66 U5.8@4006.77,793.66
  bot (thermal) w10: v5(3809.4,793.65) TP216.1@3860.47,793.66
NetC26_1: C26.1 C27.2 R38.2 TP212.1 U5.4 | length 422.8
  top w10: C27.2@4082.99,475.66 4120.05,475.66 4158.28,513.89 R38.2@4191.5,513.89 C26.1@4191.5,575.9 ; U5.4@4089.88,620 4111.22,620 4155.32,575.9 C26.1@4191.5,575.9 ; v5(4242.36,561.26) 4227.72,575.9 C26.1@4191.5,575.9
  bot (thermal) w10: v5(4242.36,561.26) 4246.3,561.26 TP212.1@4285.67,600.63
NetC27_1: C27.1 C29.2 R41.2 TP214.1 U5.1 | length 418.9
  top w10: v5(4013.11,676.34) U5.1@4013.11,620 3994.23,620 3950.13,575.9 C29.2@3911.5,575.9 R41.2@3911.5,513.89 3943.24,513.89 3981.47,475.66 C27.1@4020,475.66
  bot (thermal) w10: TP214.1@4013.11,620 v5(4013.11,676.34)
NetC30_1: C30.1 D16.2 L2.1 TP310.1 U6.12 | length 739.4
  top w10: D16.2@2023.86,668.65 v2(2099.54,668.65)
  top w20: L2.1@1937.25,993.46 1998.27,932.43 1998.27,755.27 2023.86,729.68 D16.2@2023.86,676.53
  top w30: 1789.61,975.74 1789.61,1003.3 1825.04,1038.73 1913.62,1038.73 L2.1@1929.37,1054.48 ; L2.1@1937.25,993.46 L2.1@1937.25,1062.35
  bot (thermal) w10: TP310.1@2096.69,616.38 2096.69,665.81 v2(2099.54,668.65)
NetC30_2: C30.2 TP309.1 U6.11 | length 152
  top w8: U6.11@1789.61,937.35 1818.15,937.35 1826.46,945.66 ; v2(1840.79,931.34) 1826.46,945.66 ; C30.2@1856.54,975.74 1826.46,945.66
  bot (thermal) w8: TP309.1@1836.85,978.58 1836.85,935.28 v2(1840.79,931.34)
NetC32_2: C32.2 R47.2 TP300.1 U7.2 | length 304.2
  top w10: U7.2@1112.72,280 C32.2@1240,280 ; v5(1250,152.05) R47.2@1250,200 C32.2@1250,270
  bot (thermal) w10: TP300.1@1191.18,151.81 1249.76,151.81 v5(1250,152.05)
NetC33_2: C33.2 TP301.1 U7.5 | length 163.9
  top w10: v5(858.62,445) C33.2@908.5,445 ; U7.5@907.72,380 C33.2@907.72,440
  bot (thermal) w10: TP301.1@805.35,443.15 856.77,443.15 v5(858.62,445)
NetC36_1: C36.1 C37.1 C38.2 C39.2 J18.2 J18.4 K1.4 SW1.2 TP305.1 | length 3186.2
  top w39.37: SW1.2@41.26,270 -60,371.26 C39.2@-60,540 -180,540 -250,610 -250,1465 -140,1575 235,1575 C36.1@310,1500 ; C37.1@320,1780 K1.4@320,2080 ; C36.1@340,1510 C37.1@340,1785
  bot (thermal) w10: SW1.2@41.26,270 96.77,270 TP305.1@128.19,301.42
  bot (thermal) w170: J18.4@-58.15,1905 210,1905 320,2015 K1.4@320,2080
NetC40_1: C40.1 TP408.1 U8.4 | length 175.2
  top w8: C40.1@2269.64,1728.89 2319.44,1728.89 v2(2327.52,1736.97) 2337.94,1747.39 U8.4@2401.15,1747.39
  bot (thermal) w8: v2(2327.52,1736.97) 2359.02,1736.97 TP408.1@2362.2,1740.16
NetC40_2: C40.2 TP409.1 U8.5 | length 208.7
  top w8: C40.2@2269.14,1664.89 C40.2@2271.14,1664.89 ; C40.2@2269.64,1665.9 2327.31,1665.9 v2(2328.98,1667.56) 2344.72,1683.31 2344.72,1706.93 2365.5,1727.71 U8.5@2401.15,1727.71
  bot (thermal) w8: TP409.1@2301.42,1647.87 2309.29,1647.87 v2(2328.98,1667.56)
NetC41_1: C41.1 TP419.1 U10.4 | length 180
  top w8: C41.1@3054.64,1728.89 3104.44,1728.89 v2(3112.52,1736.97) 3122.94,1747.39 U10.4@3186.14,1747.39
  bot (thermal) w8: v2@3112.52,1734.56 v2(3112.52,1736.97) 3146.42,1736.97 TP419.1@3149.61,1740.16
